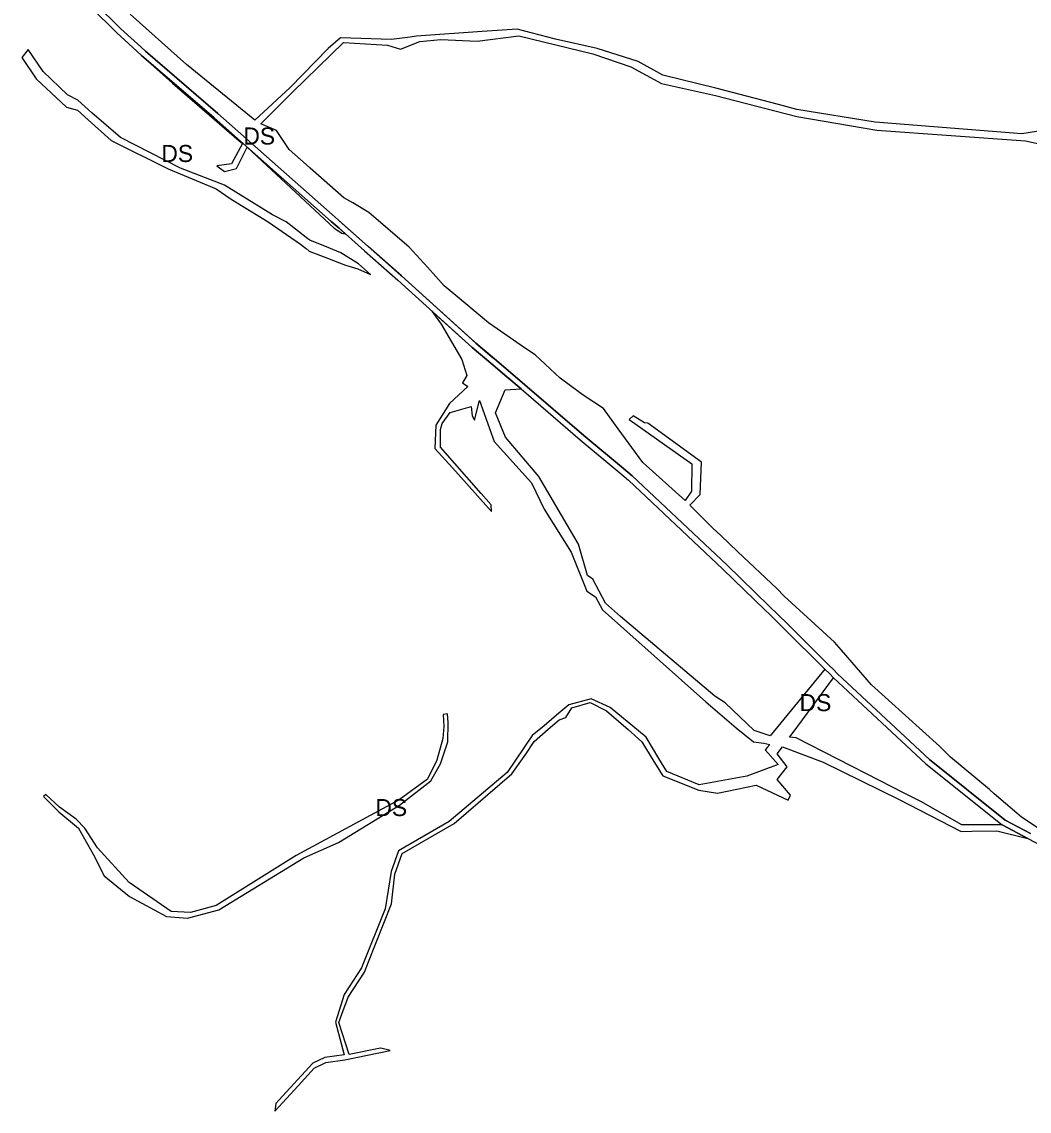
# Model space of a CAD drawing. Extents: x -477304 to -465641, y -1159113 to -1149285.
# Drawn here: x -470128 to -469597, y -1155939 to -1155364 of the extents above; entities that cross this region are included whole.
import ezdxf

# ---------------------------------------------------------------- set-up
doc = ezdxf.new("R2010")
doc.units = 0
doc.layers.add('35', color=7, linetype='Continuous')
doc.layers.add('4', color=7, linetype='Continuous')

msp = doc.modelspace()

# ---------------------------------------------------------------- linework, layer by layer
at = {"layer": '35'}
for p, q in [((-469923.46, -1155372.45), (-469933.26, -1155373.85)), ((-469920.13, -1155371.97), (-469923.46, -1155372.45)), ((-469885.47, -1155369.59), (-469920.13, -1155371.97)), ((-469888.06, -1155374.69), (-469866.1, -1155371.8)), ((-469867, -1155368.4), (-469885.47, -1155369.59)), ((-469846.86, -1155373.55), (-469867, -1155368.4)), ((-469928.65, -1155378.83), (-469918.46, -1155374.8)), ((-469824.85, -1155378.47), (-469846.86, -1155373.55)), ((-470125.01, -1155379.06), (-470128.29, -1155383.27)), ((-470116.95, -1155390.71), (-470125.01, -1155379.06)), ((-470026.86, -1155415.04), (-470065.09, -1155382.13)), ((-470063.11, -1155379.88), (-470024.9, -1155412.77)), ((-469803.32, -1155385.4), (-469824.85, -1155378.47)), ((-469790.2, -1155392.5), (-469803.32, -1155385.4)), ((-470104.25, -1155402.88), (-470116.95, -1155390.71)), ((-469762.23, -1155399.4), (-469790.2, -1155392.5)), ((-469790.93, -1155396.97), (-469762.44, -1155403.35)), ((-469729.29, -1155408.13), (-469762.23, -1155399.4)), ((-469762.44, -1155403.35), (-469719.51, -1155414.37)), ((-470098.94, -1155411.07), (-470093.25, -1155416.19)), ((-470076.31, -1155425.48), (-470091.4, -1155412.46)), ((-470024.9, -1155412.77), (-470024.89, -1155412.78)), ((-470024.89, -1155412.78), (-469963.11, -1155467.46)), ((-470093.25, -1155416.19), (-470081.12, -1155427.08)), ((-469993.96, -1155421.77), (-470002.24, -1155418.26)), ((-469987.27, -1155431.78), (-469993.96, -1155421.77)), ((-470044.57, -1155441.66), (-470076.31, -1155425.48)), ((-470013.65, -1155427.14), (-470011.89, -1155428.68)), ((-470015.13, -1155441.88), (-470009.49, -1155430.6)), ((-470009.49, -1155430.6), (-469963.47, -1155473.25)), ((-469978.24, -1155439.73), (-469987.27, -1155431.78)), ((-470025.41, -1155440.45), (-470021.46, -1155443.47)), ((-469976.16, -1155441.57), (-469978.24, -1155439.73)), ((-470021.46, -1155443.47), (-470015.13, -1155441.88)), ((-470025.87, -1155452.62), (-470017.95, -1155457.92)), ((-470017.95, -1155457.92), (-469998.32, -1155469.97)), ((-469945.29, -1155465.08), (-469953.64, -1155460)), ((-469998.32, -1155469.97), (-469981.37, -1155481.74)), ((-469988.89, -1155469.95), (-469996.16, -1155466.34)), ((-469977.53, -1155478.87), (-469988.89, -1155469.95)), ((-469963.11, -1155467.46), (-469959.31, -1155470.84)), ((-469923.92, -1155483.31), (-469945.29, -1155465.08)), ((-469960.99, -1155473.36), (-469962.97, -1155471.59)), ((-469957.76, -1155476.23), (-469960.99, -1155473.36)), ((-469959.31, -1155470.84), (-469945.6, -1155483.02)), ((-469981.37, -1155481.74), (-469979.72, -1155483.03)), ((-469976.4, -1155479.67), (-469977.53, -1155478.87)), ((-469966.45, -1155483.68), (-469976.4, -1155479.67)), ((-469979.72, -1155483.03), (-469978.86, -1155483.7)), ((-469978.86, -1155483.7), (-469978.38, -1155484.08)), ((-469978.38, -1155484.08), (-469976.75, -1155485.38)), ((-469976.75, -1155485.38), (-469967.01, -1155489.07)), ((-469959.99, -1155486.28), (-469966.45, -1155483.68)), ((-469950.65, -1155492.03), (-469959.99, -1155486.28)), ((-469945.6, -1155483.02), (-469928.49, -1155498.05)), ((-469914.39, -1155493.87), (-469923.92, -1155483.31)), ((-469967.01, -1155489.07), (-469957.62, -1155492.74)), ((-469957.62, -1155492.74), (-469956.34, -1155493.14)), ((-469956.34, -1155493.14), (-469951.13, -1155494.78)), ((-469944.43, -1155497.74), (-469950.65, -1155492.03)), ((-469951.13, -1155494.78), (-469944.43, -1155497.74)), ((-469928.49, -1155498.05), (-469928.04, -1155498.44)), ((-469928.04, -1155498.44), (-469889.52, -1155533.33)), ((-469905.53, -1155503.63), (-469914.39, -1155493.87)), ((-469895.25, -1155512.33), (-469905.53, -1155503.63)), ((-469882.18, -1155523.22), (-469895.25, -1155512.33)), ((-469890.8, -1155536.22), (-469912.01, -1155517.01)), ((-469912.01, -1155517.01), (-469907.14, -1155523.84)), ((-469889.52, -1155533.33), (-469888.82, -1155533.96)), ((-469881.01, -1155544.52), (-469890.8, -1155536.22)), ((-469888.82, -1155533.96), (-469880.34, -1155541.16)), ((-469872.44, -1155551.74), (-469881.01, -1155544.52)), ((-469844.43, -1155552.35), (-469857.58, -1155540.04)), ((-469893.54, -1155551.05), (-469895.93, -1155554.85)), ((-469895.93, -1155554.85), (-469893.13, -1155556.8)), ((-469865, -1155558.12), (-469872.44, -1155551.74)), ((-469863.05, -1155555.84), (-469831.87, -1155582.58)), ((-469893.13, -1155556.8), (-469902.79, -1155565.75)), ((-469878.55, -1155570.75), (-469873.43, -1155558.57)), ((-469873.43, -1155558.57), (-469865, -1155558.12)), ((-469821.57, -1155568.39), (-469831.7, -1155561.79)), ((-469902.79, -1155565.75), (-469909.92, -1155577.13)), ((-469898.61, -1155569.4), (-469891.39, -1155567.36)), ((-469891.39, -1155567.36), (-469890.74, -1155572.33)), ((-469889.62, -1155574.52), (-469886.97, -1155564.22)), ((-469886.97, -1155564.22), (-469879.19, -1155585.82)), ((-469902.37, -1155570.46), (-469898.61, -1155569.4)), ((-469890.74, -1155572.33), (-469889.62, -1155574.52)), ((-469873.24, -1155583.5), (-469878.55, -1155570.75)), ((-469813.78, -1155579.15), (-469821.57, -1155568.39)), ((-469805.84, -1155572.3), (-469808.05, -1155574.17)), ((-469909.92, -1155577.13), (-469910.39, -1155589.54)), ((-469907.51, -1155588.77), (-469907.4, -1155579.48)), ((-469800.84, -1155596.86), (-469813.78, -1155579.15)), ((-469808.05, -1155574.17), (-469774.89, -1155597.6)), ((-469769.79, -1155596.79), (-469798.16, -1155576.19)), ((-469855.61, -1155604.26), (-469873.24, -1155583.5)), ((-469831.87, -1155582.58), (-469810.94, -1155600.1)), ((-469886.09, -1155613.25), (-469907.51, -1155588.77)), ((-469879.19, -1155585.82), (-469859.55, -1155607.7)), ((-469810.94, -1155600.1), (-469806.42, -1155603.95)), ((-469778.43, -1155616.96), (-469800.84, -1155596.86)), ((-469770.62, -1155613.7), (-469769.79, -1155596.79)), ((-469859.55, -1155607.7), (-469852.87, -1155621.49)), ((-469880.73, -1155619.24), (-469886.09, -1155613.25)), ((-469775.99, -1155619.35), (-469770.62, -1155613.7)), ((-469880.52, -1155622.68), (-469880.73, -1155619.24)), ((-469763.9, -1155631.6), (-469775.99, -1155619.35)), ((-469759.69, -1155635.35), (-469763.9, -1155631.6)), ((-469750.68, -1155644.03), (-469759.69, -1155635.35)), ((-469730.14, -1155663.37), (-469750.68, -1155644.03)), ((-469726.17, -1155667.4), (-469730.14, -1155663.37)), ((-469812.48, -1155678.08), (-469820.48, -1155671.16)), ((-469699.65, -1155691.69), (-469726.17, -1155667.4)), ((-469762.84, -1155720.12), (-469812.48, -1155678.08)), ((-469696.08, -1155695.95), (-469699.65, -1155691.69)), ((-469680.19, -1155714.22), (-469696.08, -1155695.95)), ((-469704.83, -1155705.91), (-469720.87, -1155725.44)), ((-469702.35, -1155708.17), (-469704.83, -1155705.91)), ((-469702.76, -1155703.74), (-469700.23, -1155706.04)), ((-469644.33, -1155746.57), (-469680.19, -1155714.22)), ((-469828.09, -1155721.48), (-469839.84, -1155724.68)), ((-469757.37, -1155723.75), (-469762.84, -1155720.12)), ((-469839.84, -1155724.68), (-469845.12, -1155729.15)), ((-469841.39, -1155731.43), (-469838.29, -1155726.36)), ((-469838.29, -1155726.36), (-469828.52, -1155723.55)), ((-469720.87, -1155725.44), (-469733.64, -1155741)), ((-469903.72, -1155729.55), (-469906.15, -1155729.84)), ((-469845.12, -1155729.15), (-469852.89, -1155735.73)), ((-469850.66, -1155737.55), (-469844.98, -1155732.66)), ((-469844.98, -1155732.66), (-469841.39, -1155731.43)), ((-469723.37, -1155741.78), (-469722.11, -1155740.08)), ((-469907.49, -1155755.86), (-469903.57, -1155744.17)), ((-469742.5, -1155744.24), (-469736.9, -1155744.97)), ((-469736.9, -1155744.97), (-469733.81, -1155745.56)), ((-469733.81, -1155745.56), (-469735.15, -1155747.16)), ((-469869.93, -1155761.1), (-469862.48, -1155750.78)), ((-469735.15, -1155747.16), (-469736.24, -1155748.48)), ((-469736.24, -1155748.48), (-469729.48, -1155756.12)), ((-469729.9, -1155750.59), (-469727.13, -1155746.85)), ((-469724.66, -1155757.38), (-469729.9, -1155750.59)), ((-469727.13, -1155746.85), (-469705.6, -1155754.98)), ((-469638.52, -1155752.25), (-469644.33, -1155746.57)), ((-469912.64, -1155764.83), (-469907.49, -1155755.86)), ((-469705.6, -1155754.98), (-469665.96, -1155774.47)), ((-469649.55, -1155753.64), (-469609.68, -1155785.58)), ((-469618.01, -1155769.41), (-469638.52, -1155752.25)), ((-469771.11, -1155766.91), (-469788.11, -1155759.97)), ((-469663.38, -1155771.16), (-469675.92, -1155764.72)), ((-470116.82, -1155773.05), (-470108.82, -1155781.21)), ((-469771.19, -1155769.75), (-469761.34, -1155771.33)), ((-469724.14, -1155775.09), (-469722.84, -1155772.34)), ((-469665.96, -1155774.47), (-469632.84, -1155791.46)), ((-469654.1, -1155775.65), (-469663.38, -1155771.16)), ((-469615.46, -1155771.61), (-469618.01, -1155769.41)), ((-469603.57, -1155781.95), (-469615.46, -1155771.61)), ((-470099.59, -1155785.05), (-470108.37, -1155778.73)), ((-469609.68, -1155785.58), (-469596.32, -1155792.58)), ((-469601.15, -1155784.05), (-469603.57, -1155781.95)), ((-469587.05, -1155793.25), (-469601.15, -1155784.05)), ((-469632.84, -1155791.46), (-469627.36, -1155791.4)), ((-469627.36, -1155791.4), (-469614.12, -1155791.26)), ((-469614.12, -1155791.26), (-469597.72, -1155795.23)), ((-469597.72, -1155795.23), (-469611.33, -1155788.1)), ((-470090.56, -1155803.77), (-470084.83, -1155815)), ((-469933.36, -1155829.77), (-469931.55, -1155814.07)), ((-469945.45, -1155860.35), (-469933.36, -1155829.77)), ((-470052.06, -1155836.39), (-470040.91, -1155837.25)), ((-470040.91, -1155837.25), (-470024.43, -1155832.84)), ((-469961.02, -1155892.33), (-469959.44, -1155887.94)), ((-469955.61, -1155909.22), (-469961.02, -1155892.33)), ((-469939.14, -1155905.91), (-469955.61, -1155909.22)), ((-469939.03, -1155905.89), (-469939.14, -1155905.91)), ((-469933.96, -1155907.13), (-469939.03, -1155905.89)), ((-469958.23, -1155909.34), (-469968.5, -1155910.82)), ((-469957.99, -1155912.01), (-469933.96, -1155907.13)), ((-469994.88, -1155939.08), (-469982.51, -1155925.62)), ((-469994.3, -1155934.95), (-469994.88, -1155939.08)), ((-469992.71, -1155933.22), (-469994.3, -1155934.95))]:
    msp.add_line(p, q, dxfattribs=at)
for points in [[(-470125.75, -1155318.53), (-470108.37, -1155335.89), (-470103.26, -1155340.99), (-470076.13, -1155368.14), (-470065.57, -1155377.66), (-470063.11, -1155379.88)], [(-470005.39, -1155416.4), (-470041.36, -1155387.01), (-470071.1, -1155360.45)], [(-469866.1, -1155371.8), (-469827.2, -1155381.34), (-469807.13, -1155388.25), (-469790.93, -1155396.97)], [(-470002.24, -1155418.26), (-469985.42, -1155401.43), (-469958.72, -1155375.4), (-469935.51, -1155376.67), (-469928.65, -1155378.83)], [(-469933.26, -1155373.85), (-469960.17, -1155372.94), (-469966.79, -1155378.58)], [(-469918.46, -1155374.8), (-469907.36, -1155373.76), (-469888.06, -1155374.69)], [(-470128.29, -1155383.27), (-470120.74, -1155394.58), (-470104.8, -1155409.38), (-470098.94, -1155411.07)], [(-470065.09, -1155382.13), (-470048.81, -1155396.82), (-470013.65, -1155427.14)], [(-469966.79, -1155378.58), (-469986.78, -1155399.04), (-470005.39, -1155416.4)], [(-470091.4, -1155412.46), (-470098.71, -1155405.76), (-470104.25, -1155402.88)], [(-469549.11, -1155415.21), (-469600.95, -1155423.61), (-469678.22, -1155417.42), (-469719.65, -1155410.69), (-469729.29, -1155408.13)], [(-469962.97, -1155471.59), (-469965.1, -1155469.7), (-470026.86, -1155415.04)], [(-469719.51, -1155414.37), (-469677.45, -1155421.57), (-469599.04, -1155427.21), (-469590.2, -1155429.14), (-469583.53, -1155432.02)], [(-470081.12, -1155427.08), (-470051.06, -1155442.05), (-470025.87, -1155452.62)], [(-470011.89, -1155428.68), (-470017.75, -1155439.39), (-470025.41, -1155440.45)], [(-469996.16, -1155466.34), (-470021.38, -1155450.61), (-470044.57, -1155441.66)], [(-469953.64, -1155460), (-469958.38, -1155457.23), (-469976.16, -1155441.57)], [(-469963.47, -1155473.25), (-469959.52, -1155475.87), (-469957.76, -1155476.23)], [(-469907.14, -1155523.84), (-469896.28, -1155542.6), (-469893.54, -1155551.05)], [(-469857.58, -1155540.04), (-469862.61, -1155536.71), (-469882.18, -1155523.22)], [(-469880.34, -1155541.16), (-469879.07, -1155542.23), (-469870.5, -1155549.45), (-469863.05, -1155555.84)], [(-469831.7, -1155561.79), (-469834.15, -1155559.94), (-469844.43, -1155552.35)], [(-469907.4, -1155579.48), (-469906.63, -1155576.37), (-469902.37, -1155570.46)], [(-469798.16, -1155576.19), (-469799.96, -1155576.02), (-469805.84, -1155572.3)], [(-469910.39, -1155589.54), (-469901.15, -1155599.74), (-469880.52, -1155622.68)], [(-469774.89, -1155597.6), (-469775.06, -1155612.07), (-469778.43, -1155616.96)], [(-469820.48, -1155671.16), (-469827.22, -1155658.45), (-469830.02, -1155656.58), (-469834.64, -1155639.91), (-469855.61, -1155604.26)], [(-469806.42, -1155603.95), (-469756.48, -1155650.93), (-469734.08, -1155672.65)], [(-469852.87, -1155621.49), (-469838.62, -1155644.12), (-469830.38, -1155664.69)], [(-469830.38, -1155664.69), (-469825.78, -1155667.81), (-469822, -1155674.68)], [(-469822, -1155674.68), (-469767.63, -1155723.15), (-469751.53, -1155736.94), (-469742.5, -1155744.24)], [(-469734.08, -1155672.65), (-469724.54, -1155682.08), (-469702.76, -1155703.74)], [(-469722.11, -1155740.08), (-469700.2, -1155710.51), (-469702.35, -1155708.17)], [(-469700.23, -1155706.04), (-469698.07, -1155708.39), (-469649.55, -1155753.64)], [(-469788.11, -1155759.97), (-469792.35, -1155753.08), (-469799.09, -1155741.7), (-469817.99, -1155726.08), (-469828.09, -1155721.48)], [(-469828.52, -1155723.55), (-469819.94, -1155727.83), (-469808.43, -1155737.65)], [(-469733.64, -1155741), (-469742.01, -1155738.26), (-469757.37, -1155723.75)], [(-469906.15, -1155729.84), (-469905.77, -1155736.17), (-469906.33, -1155742.48)], [(-469903.57, -1155744.17), (-469903.38, -1155734.05), (-469903.72, -1155729.55)], [(-469852.89, -1155735.73), (-469859.07, -1155740.96), (-469872.33, -1155760.4), (-469902.95, -1155786.27), (-469929.6, -1155801.79), (-469933.46, -1155812.64)], [(-469862.48, -1155750.78), (-469858.16, -1155744), (-469850.66, -1155737.55)], [(-469808.43, -1155737.65), (-469801.22, -1155744.17), (-469795.02, -1155754.69)], [(-469906.33, -1155742.48), (-469909.42, -1155753.99), (-469914.33, -1155763.94), (-469929.2, -1155774.83), (-469983.64, -1155804.16)], [(-469675.92, -1155764.72), (-469719.89, -1155742.15), (-469723.37, -1155741.78)], [(-469795.02, -1155754.69), (-469790.15, -1155762.23), (-469771.19, -1155769.75)], [(-469729.48, -1155756.12), (-469745.92, -1155762.31), (-469771.11, -1155766.91)], [(-469722.84, -1155772.34), (-469729.9, -1155764.1), (-469724.66, -1155757.38)], [(-469931.55, -1155814.07), (-469927.69, -1155803.1), (-469900.26, -1155787.38), (-469869.93, -1155761.1)], [(-469961.24, -1155797.41), (-469929.14, -1155777.62), (-469912.64, -1155764.83)], [(-469761.34, -1155771.33), (-469741, -1155767.13), (-469724.14, -1155775.09)], [(-470108.37, -1155778.73), (-470115.66, -1155772.01), (-470116.82, -1155773.05)], [(-469611.33, -1155788.1), (-469632.56, -1155788.04), (-469654.1, -1155775.65)], [(-470108.82, -1155781.21), (-470098.4, -1155789.7), (-470090.56, -1155803.77)], [(-470088.37, -1155800.1), (-470095.01, -1155789.7), (-470099.59, -1155785.05)], [(-470024.43, -1155832.84), (-469979.54, -1155805.5), (-469961.24, -1155797.41)], [(-469983.64, -1155804.16), (-470025.84, -1155830.57), (-470039.26, -1155834.18), (-470049.46, -1155833.73), (-470071.72, -1155818.37), (-470088.37, -1155800.1)], [(-470084.83, -1155815), (-470071.57, -1155825.85), (-470052.06, -1155836.39)], [(-469933.46, -1155812.64), (-469936.67, -1155832.4), (-469949.15, -1155863.48), (-469958.23, -1155877.53)], [(-469959.44, -1155887.94), (-469956.21, -1155878.87), (-469947.58, -1155865.76), (-469945.45, -1155860.35)], [(-469958.23, -1155877.53), (-469962.92, -1155892.16), (-469958.23, -1155909.34)], [(-469968.5, -1155910.82), (-469974.75, -1155913.74), (-469992.71, -1155933.22)], [(-469982.51, -1155925.62), (-469974.17, -1155916.45), (-469967.93, -1155913.41), (-469957.99, -1155912.01)]]:
    msp.add_lwpolyline(points, dxfattribs=at)
at = {"layer": '4'}
for p, q in [((-470065.09, -1155382.13), (-470026.86, -1155415.04)), ((-470024.9, -1155412.77), (-470063.11, -1155379.88)), ((-470024.89, -1155412.78), (-470024.9, -1155412.77)), ((-469963.11, -1155467.46), (-470024.89, -1155412.78)), ((-469888.82, -1155533.96), (-469928.04, -1155498.44)), ((-469930.04, -1155500.68), (-469890.8, -1155536.22)), ((-469890.8, -1155536.22), (-469881.01, -1155544.52)), ((-469831.87, -1155582.58), (-469863.05, -1155555.84)), ((-469833.81, -1155584.87), (-469812.88, -1155602.39)), ((-469810.94, -1155600.1), (-469831.87, -1155582.58)), ((-469812.88, -1155602.39), (-469808.42, -1155606.19)), ((-469806.42, -1155603.95), (-469810.94, -1155600.1)), ((-469808.42, -1155606.19), (-469758.55, -1155653.1)), ((-469758.55, -1155653.1), (-469736.18, -1155674.79)), ((-469700.23, -1155706.04), (-469702.76, -1155703.74)), ((-469609.68, -1155785.58), (-469649.55, -1155753.64)), ((-469596.32, -1155792.58), (-469609.68, -1155785.58)), ((-469597.72, -1155795.23), (-469551.15, -1155820.19))]:
    msp.add_line(p, q, dxfattribs=at)
for points in [[(-470063.11, -1155379.88), (-470065.57, -1155377.66), (-470076.13, -1155368.14), (-470103.26, -1155340.99), (-470108.37, -1155335.89), (-470125.75, -1155318.53)], [(-470110.49, -1155338.01), (-470105.38, -1155343.11), (-470078.2, -1155370.32)], [(-470078.2, -1155370.32), (-470067.58, -1155379.89), (-470065.09, -1155382.13)], [(-470026.86, -1155415.04), (-469965.1, -1155469.7), (-469960.99, -1155473.36)], [(-469928.04, -1155498.44), (-469945.6, -1155483.02), (-469963.11, -1155467.46)], [(-469960.99, -1155473.36), (-469947.59, -1155485.27), (-469930.04, -1155500.68)], [(-469863.05, -1155555.84), (-469870.5, -1155549.45), (-469879.07, -1155542.23), (-469888.82, -1155533.96)], [(-469881.01, -1155544.52), (-469872.44, -1155551.74), (-469865, -1155558.12), (-469833.81, -1155584.87)], [(-469734.08, -1155672.65), (-469756.48, -1155650.93), (-469806.42, -1155603.95)], [(-469736.18, -1155674.79), (-469734.06, -1155676.84), (-469726.65, -1155684.21)], [(-469702.76, -1155703.74), (-469724.54, -1155682.08), (-469734.08, -1155672.65)], [(-469726.65, -1155684.21), (-469704.83, -1155705.91), (-469702.35, -1155708.17), (-469700.2, -1155710.51), (-469651.51, -1155755.91)], [(-469649.55, -1155753.64), (-469698.07, -1155708.39), (-469700.23, -1155706.04)], [(-469651.51, -1155755.91), (-469611.33, -1155788.1), (-469597.72, -1155795.23)]]:
    msp.add_lwpolyline(points, dxfattribs=at)

# ---------------------------------------------------------------- texts
at = {"layer": '35'}
for p in [(-470011.43, -1155429.18), (-470054.68, -1155438.4), (-469718.1, -1155728.05), (-469941.81, -1155783.4)]:
    msp.add_text('DS', height=9, dxfattribs=at).set_placement(p)

doc.saveas('drawing.dxf')
